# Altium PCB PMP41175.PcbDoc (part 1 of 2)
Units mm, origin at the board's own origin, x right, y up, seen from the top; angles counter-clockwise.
Board outline 50 x 29 mm, 6 copper layers (Top Layer, Signal Layer 1, Signal Layer 2, Signal Layer 3, Signal Layer 4, Bottom Layer), stack 1.56 mm thick; 56 components, 26 nets, 110 pads, 28 vias.
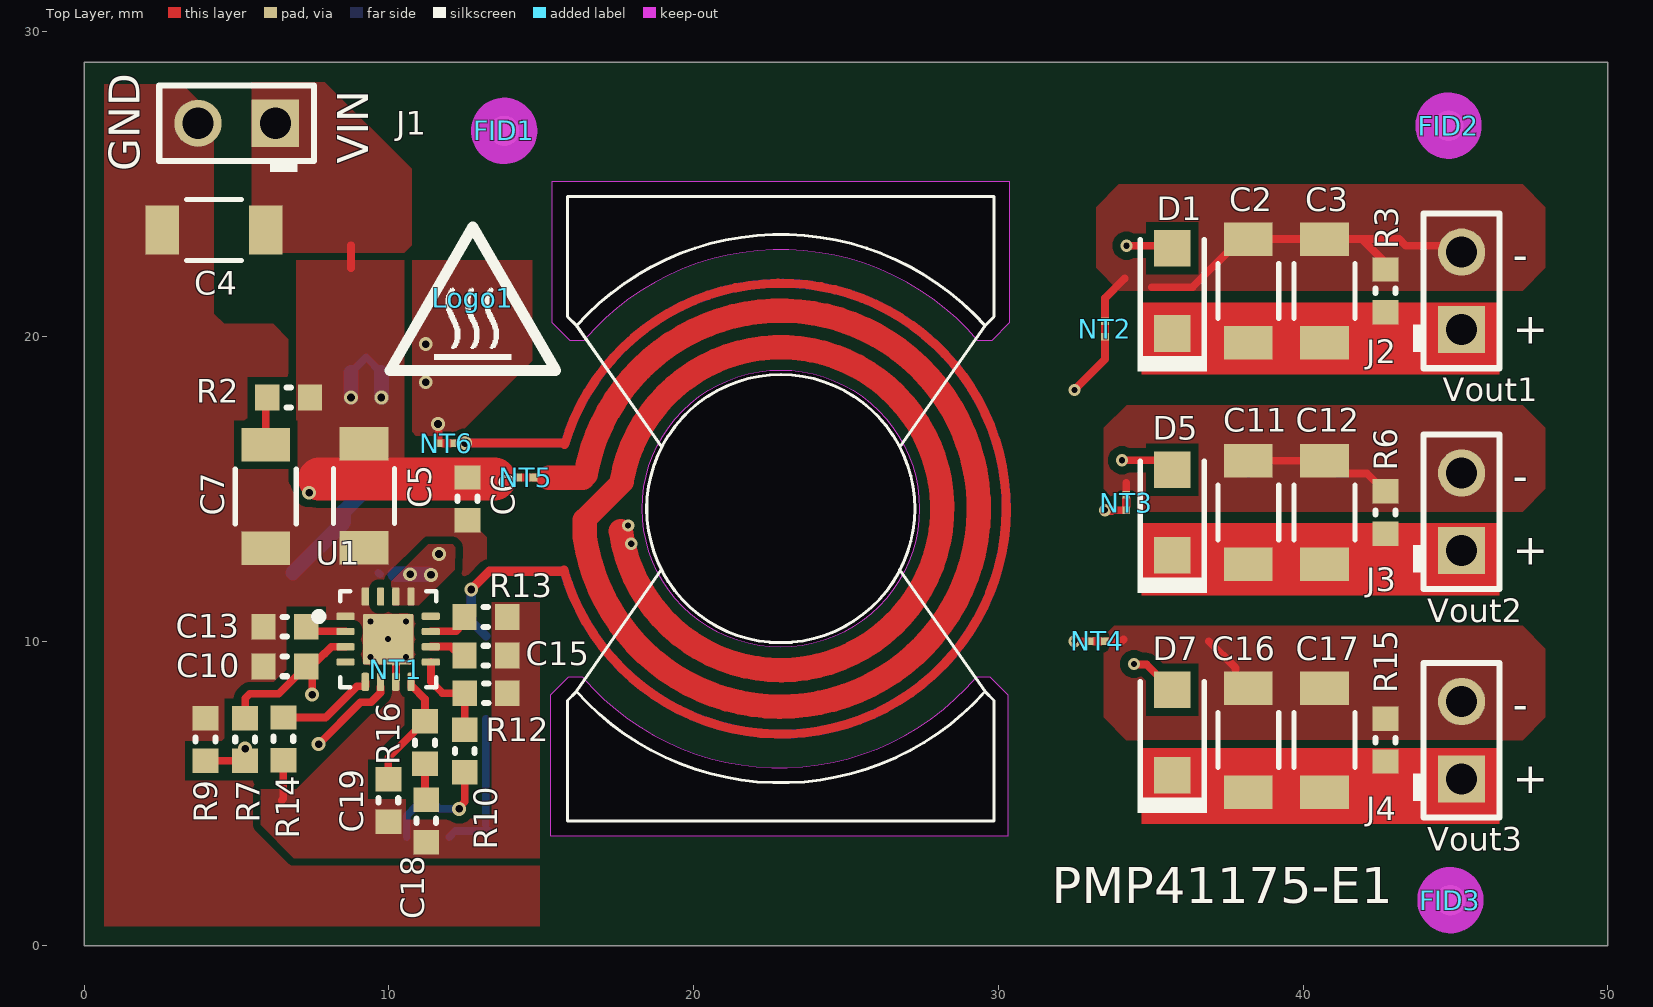
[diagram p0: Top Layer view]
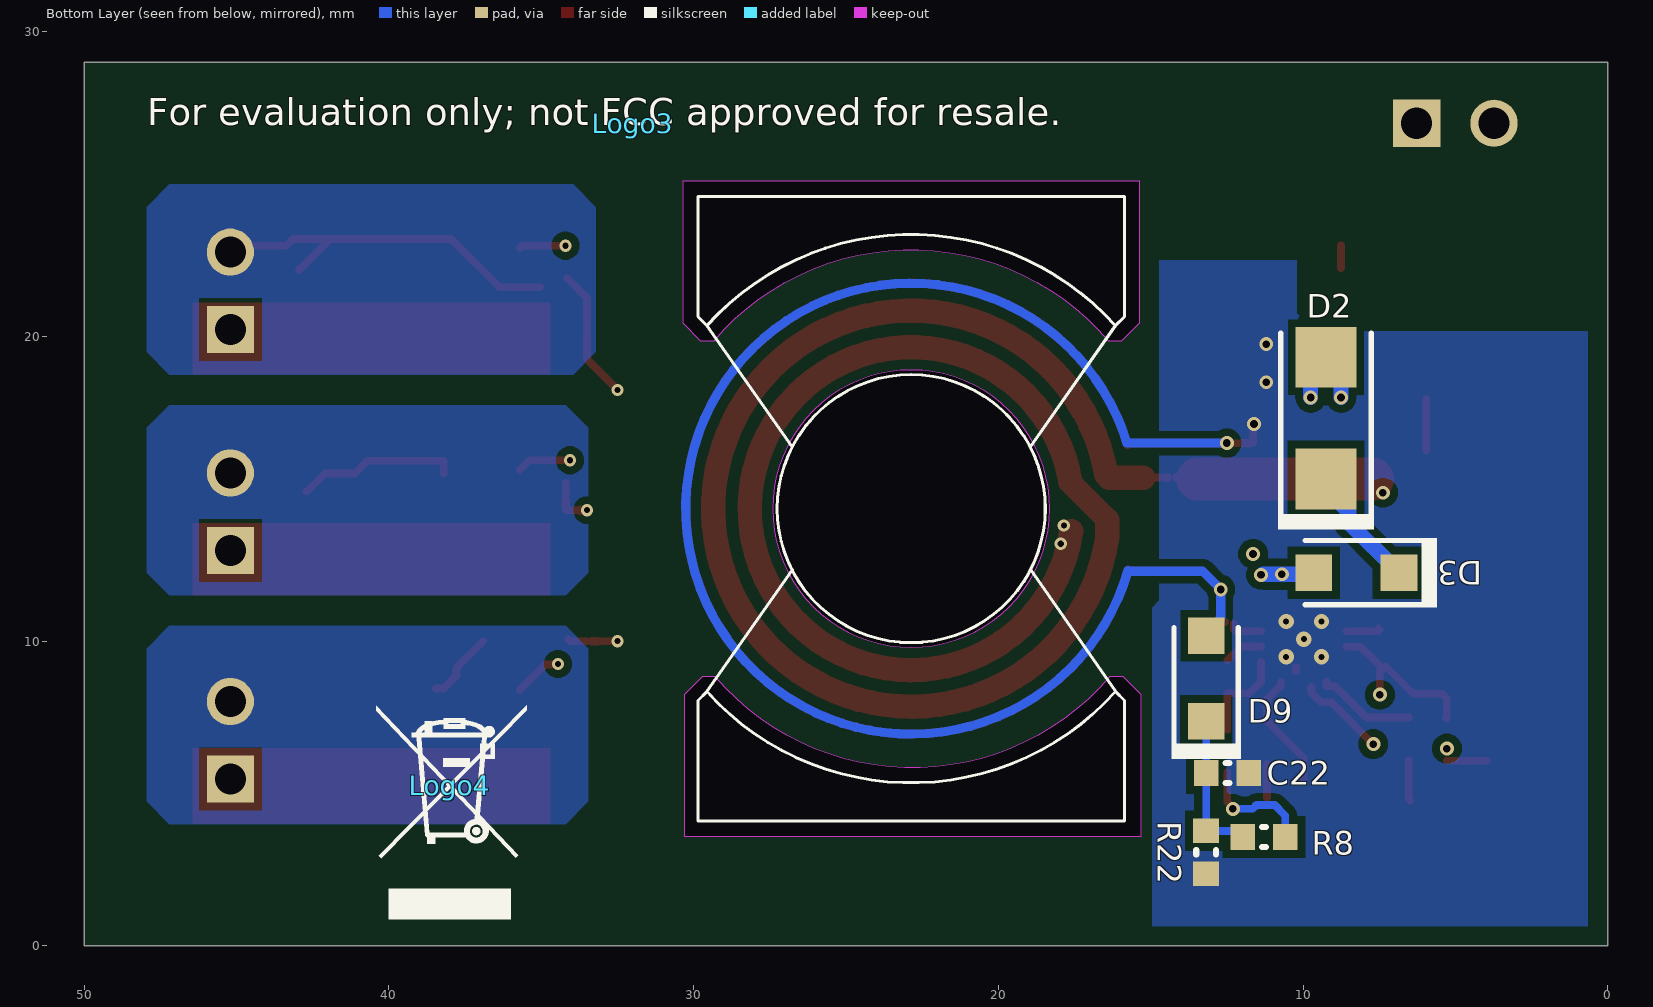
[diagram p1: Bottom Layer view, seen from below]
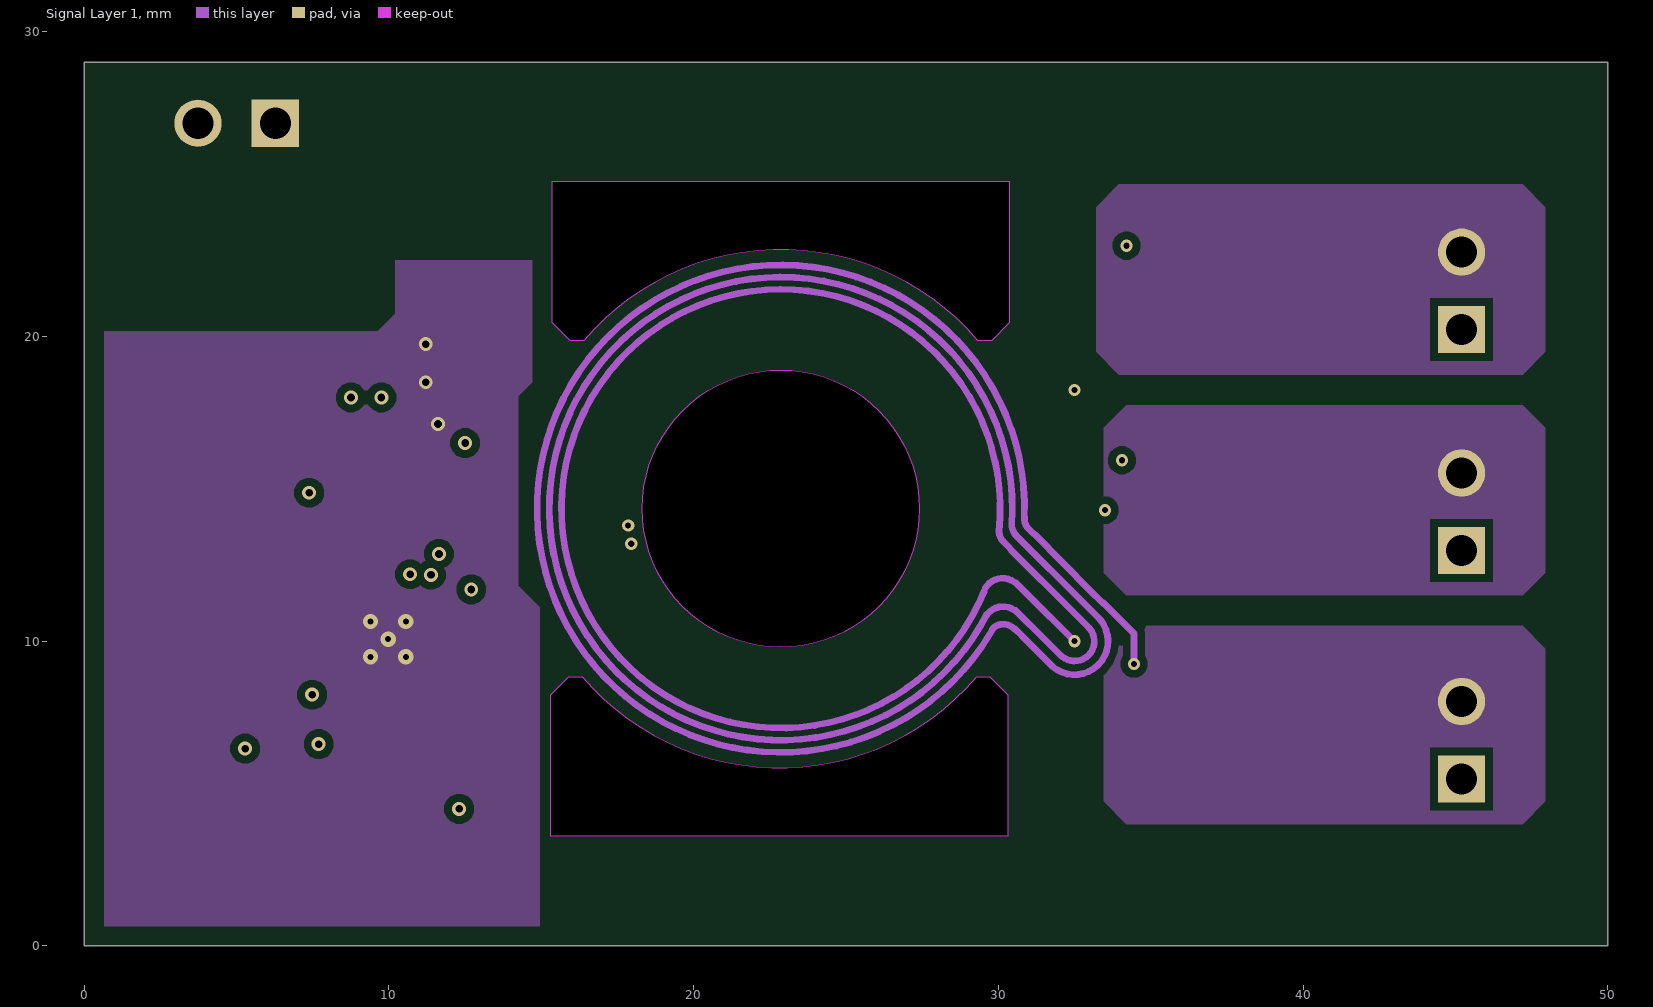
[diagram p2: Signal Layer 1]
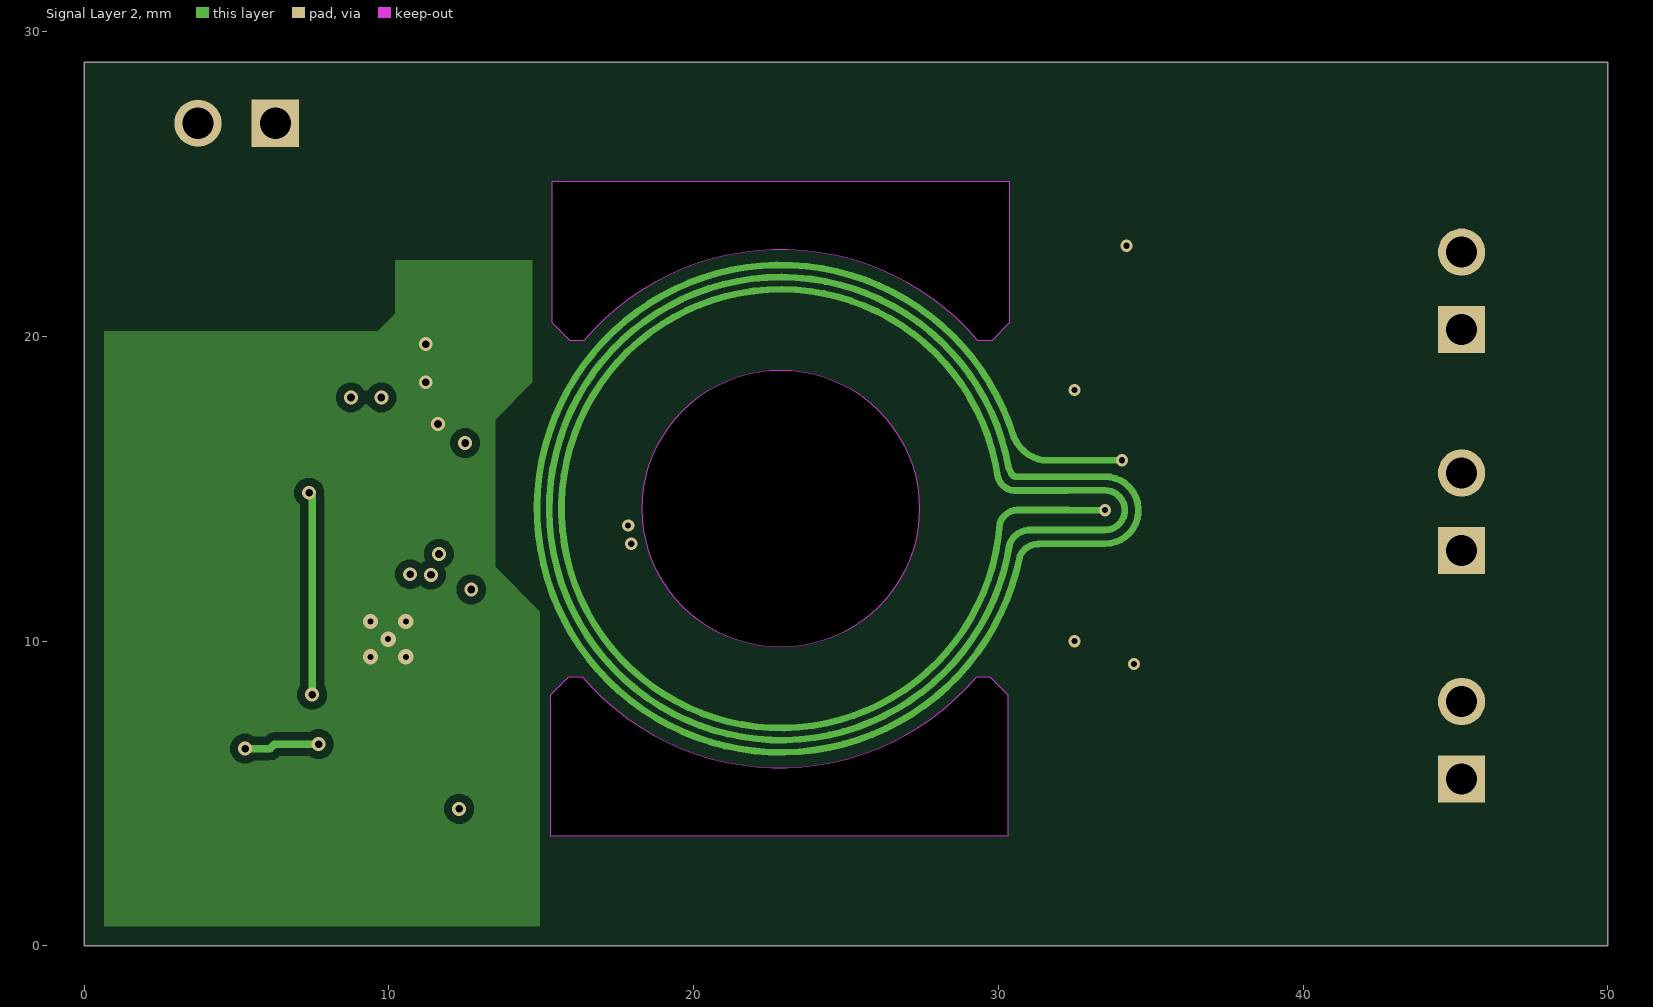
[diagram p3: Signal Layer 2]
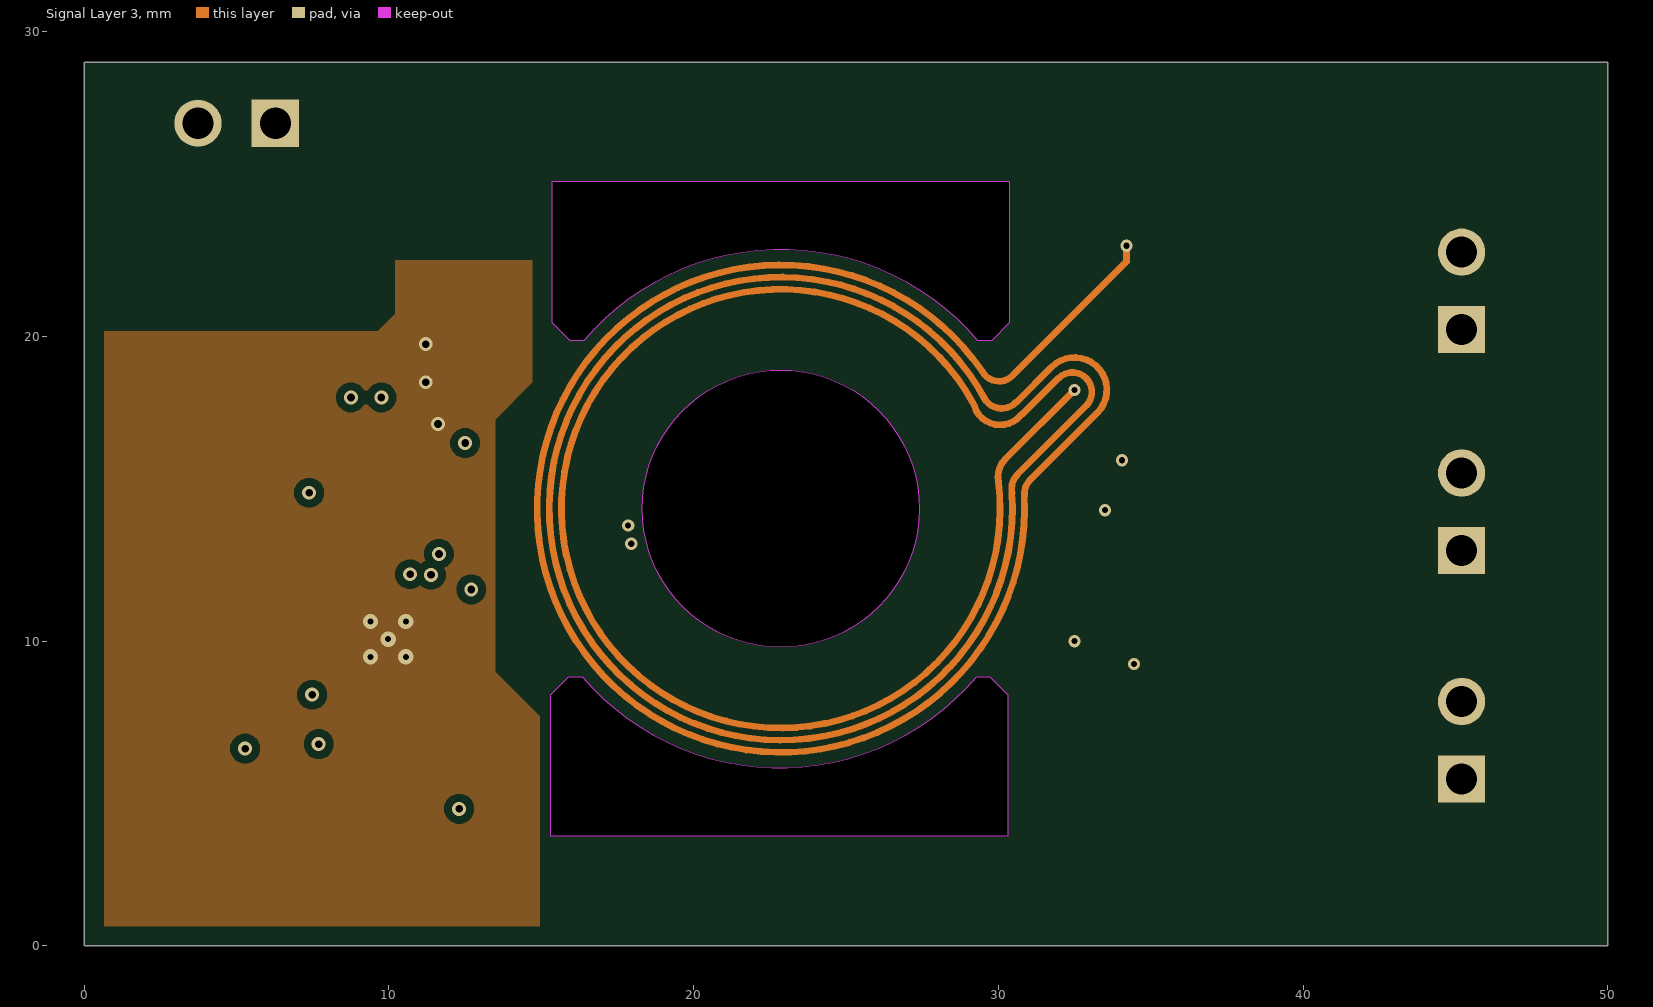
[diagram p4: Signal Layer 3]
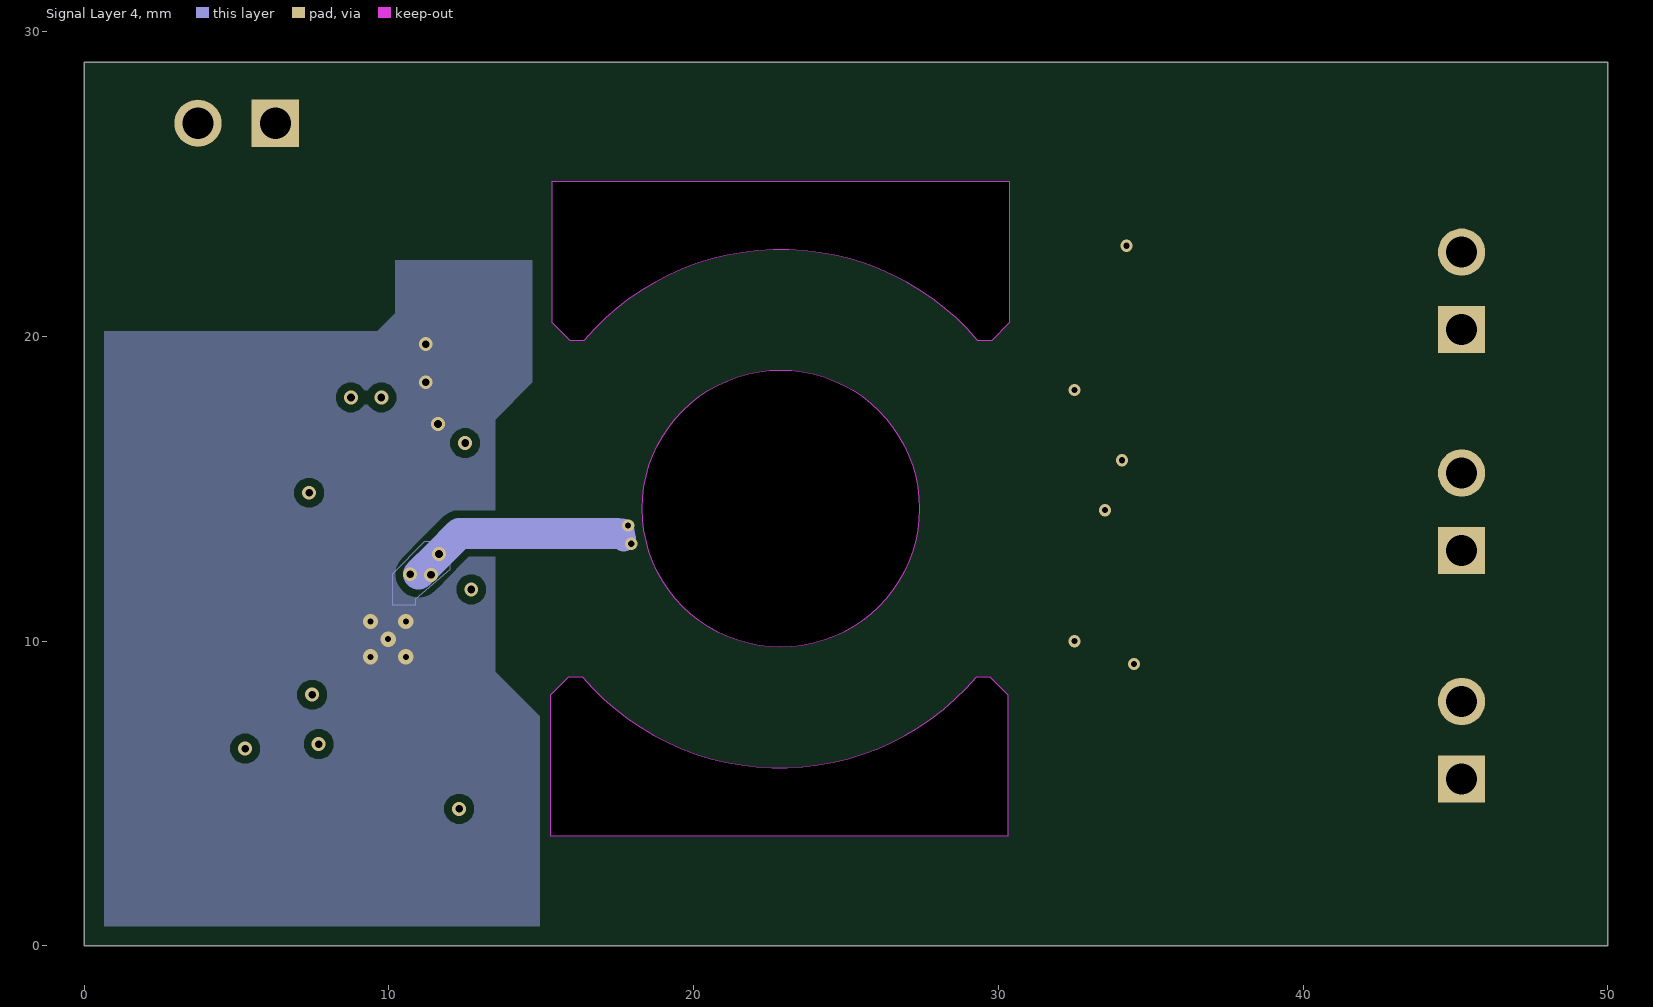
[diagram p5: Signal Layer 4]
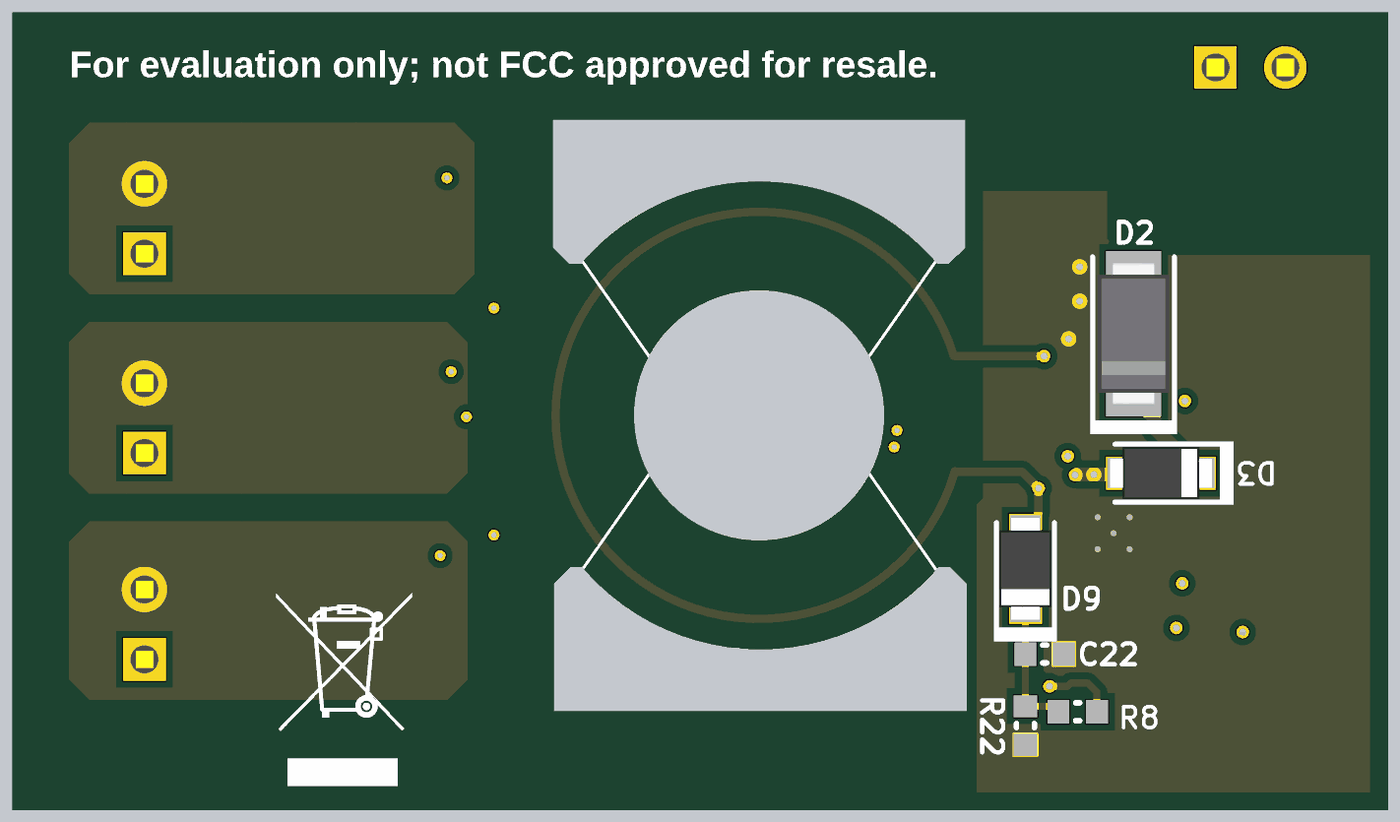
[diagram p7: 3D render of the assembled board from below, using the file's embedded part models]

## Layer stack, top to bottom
Top Solder: solder mask 0.0127, Solder Resist, Dk 3.5
Top Layer: signal copper 0.0356
Dielectric 1: prepreg 0.1778, FR-4 High Tg, Dk 4.2
Signal Layer 1: signal copper 0.0356
Dielectric 2: core 0.3556, FR-4 High Tg, Dk 4.2
Signal Layer 2: signal copper 0.0356
Dielectric 4: prepreg 0.2794, FR-4 High Tg, Dk 4.2
Signal Layer 3: signal copper 0.0356
Dielectric 5: core 0.3556, FR-4 High Tg, Dk 4.2
Signal Layer 4: signal copper 0.0356
Dielectric 3: prepreg 0.1778, FR-4 High Tg, Dk 4.2
Bottom Layer: signal copper 0.0356
Bottom Solder: solder mask 0.0127, Solder Resist, Dk 3.5

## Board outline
0,0 50,0 50,29 0,29
cut-out: 22.86,9.801 cw(c22.86,14.351) 18.31,14.351 cw(c22.86,14.351) 22.86,18.901 cw(c22.86,14.351) 27.41,14.351 cw(c22.86,14.351)
cut-out: 15.951,19.865 15.36,20.451 15.36,25.101 30.36,25.101 30.36,20.451 29.784,19.865 29.769,19.863 29.337,19.863 29.331,19.862 ccw(c22.86,14.351) 16.39,19.863 16.383,19.863
cut-out: 15.316,3.594 15.316,8.244 15.899,8.829 15.907,8.832 16.339,8.832 16.35,8.826 ccw(c22.816,14.344) 29.289,8.835 29.293,8.832 29.724,8.832 30.316,8.244 30.316,3.594

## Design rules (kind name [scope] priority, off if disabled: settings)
AcuteAngle [All] p1: minimum=4.50000000000000E+0001 checktracksonly=FALSE
AssemblyTestPointUsage [All] p1: valid=2
BoardOutlineClearance BoardOutlineClearance_MountingHoles [OnCopper and InComponentClass('Mounting Holes')] p1: gap=1 ignorepadtopadclearanceinfootprint=FALSE
BoardOutlineClearance BoardOutlineClearance_Poly [OnCopper and IsPoly] p2: gap=0.635 ignorepadtopadclearanceinfootprint=FALSE
BoardOutlineClearance [OnCopper and Not InComponentClass('Logo') and not InComponentClass('FiducialMark') and not InRegion(1000,500,4000,800) and not InPoly] p3: gap=0.279 ignorepadtopadclearanceinfootprint=FALSE
Clearance Clearance_Keepouts [((IsTrack Or IsArc) And Not InPoly) And IsFree and IsKeepOut vs ((IsTrack Or IsArc) And Not InPoly) And IsFree and IsKeepOut] p1: gap=0 ignorepadtopadclearanceinfootprint=FALSE
Clearance Clearance_Poly [InPolygon] p2: gap=0.254 ignorepadtopadclearanceinfootprint=TRUE
Clearance Clearance_FiducialMark [IsKeepOut and InComponentClass('FiducialMark') vs IsPad and InComponentClass('FiducialMark')] p3: gap=0 ignorepadtopadclearanceinfootprint=FALSE
Clearance [All] p4: gap=0.2 ignorepadtopadclearanceinfootprint=TRUE
ComponentClearance ComponentClearance_NT [InComponent('NT1')] p1: gap=-0.025 collisioncheckmode=3 verticalgap=0.254 showdistances=FALSE
ComponentClearance ComponentClearance_MountingHoles_FiducialMarks [InComponentClass('Mounting Holes') vs InComponentClass('FiducialMark')] p2: gap=1.27 collisioncheckmode=3 verticalgap=0.254 showdistances=FALSE
ComponentClearance ComponentClearance_Shunt [InComponentClass('Header') vs InComponentClass('Shunt')] p3: gap=0 collisioncheckmode=3 verticalgap=0 showdistances=FALSE
ComponentClearance ComponentClearance_Logo [InComponentClass('Logo')] p4: gap=0.762 collisioncheckmode=3 verticalgap=0.254 showdistances=FALSE
ComponentClearance ComponentClearance_ScrewToNut [(HasFootprint('NY PMS 440 0025 PH')) vs (HasFootprint('Keystone_1902C'))] p5: gap=0.127 collisioncheckmode=3 verticalgap=0.254 showdistances=FALSE
ComponentClearance ComponentClearance_MountingHoles [InComponentClass('Mounting Holes')] p6: gap=2.54 collisioncheckmode=3 verticalgap=2540 showdistances=FALSE
ComponentClearance ComponentClearance_SmallPassives [HasFootprint('0201*') or HasFootprint('0402*') or HasFootprint('0508') or HasFootprint('0603*') or HasFootprint('0612') or HasFootprint('0805*') or HasFootprint('0815*') or HasFootprint('0830*') or HasFootprint('1206*') or HasFootprint('1210*') or HasFootprint('1808*') or HasFootprint('1812*') or HasFootprint('1825*') or HasFootprint('2010*') or HasFootprint('2220*') or HasFootprint('2225*') or HasFootprint('2512*') or HasFootprint('2728*') or HasFootprint('3518*') vs HasFootprint('0201*') or HasFootprint('0402*') or HasFootprint('0508') or HasFootprint('0603*') or HasFootprint('0612') or HasFootprint('0805*') or HasFootprint('0815*') or HasFootprint('0830*') or HasFootprint('1206*') or HasFootprint('1210*') or HasFootprint('1808*') or HasFootprint('1812*') or HasFootprint('1825*') or HasFootprint('2010*') or HasFootprint('2220*') or HasFootprint('2225*') or HasFootprint('2512*') or HasFootprint('2728*') or HasFootprint('3518*')] p7: gap=0.254 collisioncheckmode=3 verticalgap=0.254 showdistances=FALSE
ComponentClearance ComponentClearance_THtoSMT [IsThruComponent vs IsSMTComponent] p8: gap=0.762 collisioncheckmode=3 verticalgap=0.762 showdistances=FALSE
ComponentClearance ComponentClearance_THtoTH [IsThruComponent vs IsThruComponent] p9: gap=0.508 collisioncheckmode=3 verticalgap=0.762 showdistances=FALSE
ComponentClearance [All] p10: gap=0.254 collisioncheckmode=3 verticalgap=0.254 showdistances=FALSE
DiffPairsRouting [All] p1: maxlimit=2.54 minlimit=0.254 mostfreqgap=0.254 toplayer_minwidth=0.381 toplayer_maxwidth=0.381 toplayer_prefwidth=0.381 midlayer1_minwidth=0.381 midlayer1_maxwidth=0.381 midlayer1_prefwidth=0.381 midlayer2_minwidth=0.381 midlayer2_maxwidth=0.381 midlayer2_prefwidth=0.381 midlayer3_minwidth=0.381 midlayer3_maxwidth=0.381 midlayer3_prefwidth=0.381 midlayer4_minwidth=0.381 midlayer4_maxwidth=0.381 midlayer4_prefwidth=0.381 bottomlayer_minwidth=0.381 bottomlayer_maxwidth=0.381 bottomlayer_prefwidth=0.381 maxuncoupledlength=25.4
FabricationTestPointUsage TestPointUsage [All] p1: valid=2 allowmultiple=FALSE
FabricationTestpoint Testpoint [All] p1: side=3 testpointundercomponent=TRUE minsize=1.016 maxsize=2.54 preferedsize=1.524 minholesize=0 maxholesize=1.016 preferedholesize=0.813 testpointgrid=0.025 allowsidetop=TRUE allowsidebottom=TRUE usegrid=TRUE gridtolerance=0
FanoutControl Fanout_LCC [IsLCC] p1: bgadir=Out bgaviamode=Centered fanoutstyle=Auto fanoutdirection=Alternating viagrid=0.025 // Fanout_LCC (Default Rule)
FanoutControl Fanout_BGA [IsBGA] p2: bgadir=Out bgaviamode=Centered fanoutstyle=Auto fanoutdirection=Alternating viagrid=0.025 // Fanout_BGA (Default Rule)
FanoutControl Fanout_Default [All] p4: bgadir=Out bgaviamode=Centered fanoutstyle=Auto fanoutdirection=Alternating viagrid=0.025 // Fanout_Default (Default Rule)
FanoutControl Fanout_Small [(CompPinCount < 5)] p5: bgadir=Out bgaviamode=Centered fanoutstyle=Auto fanoutdirection=OutThenIn viagrid=0.025 // Fanout_Small (Default Rule)
HoleSize [All] p1: absolutevalues=TRUE maxlimit=6.375 minlimit=0.2 maxpercent=80.000 minpercent=20.000
MinimumAnnularRing MinimumAnnularRing_ThermalPadVias [IsVia and InAnyComponent] p1: minimumring=0.15
MinimumAnnularRing [All] p2: minimumring=0.1
MinimumSolderMaskSliver MinimumSolderMaskSliver_Logo [InComponentClass('Logo') vs InComponentClass('Logo')] p1: minsoldermaskwidth=0.018
MinimumSolderMaskSliver [All] p2: minsoldermaskwidth=0.1
PlaneConnect [All] p1: planeconnectstyle=Relief reliefexpansion=0.254 reliefentries=4 reliefconductorwidth=0.254 reliefairgap=0.254
PolygonConnect [All] p1: connectstyle=Direct reliefconductorwidth=0.254 reliefentries=4 polygonreliefangle="90 Angle" airgapwidth=0.254
RoutingVias ThermalPadVias [IsVia and InAnyComponent] p1: holewidth=0.2 width=0.5 viastyle="Through Hole" minholewidth=0.2 minwidth=0.5 maxholewidth=0.33 maxwidth=0.6
RoutingVias [All] p2: holewidth=0.406 width=0.864 viastyle="Through Hole" minholewidth=0.2 minwidth=0.4 maxholewidth=1.016 maxwidth=1.651
SilkToBoardRegionClearance [Not ((IsComment or IsDesignator) And (Hide <> 'False')) and not InRegion(1000,500,4000,800)] p1:
SilkToSilkClearance SilkToSilkClearance_Pb-FreeLogo [(HasFootprint('Pb-Free_Overlay_Medium') OR HasFootprint('Pb-Free_Overlay_Small')) vs (HasFootprint('Pb-Free_Overlay_Medium') OR HasFootprint('Pb-Free_Overlay_Small'))] p1: silktosilkclearance=0
SilkToSilkClearance [All] p2: silktosilkclearance=0.1
SilkToSolderMaskClearance SilkToComponentPadClearance [(IsPad or IsFill or IsRegion) and InAnycomponent] p1: minsilkscreentomaskgap=0 clearancetoexposedcopper=TRUE
SilkToSolderMaskClearance "Silk to Solder Mask Opening" [All] p2: minsilkscreentomaskgap=0.025 clearancetoexposedcopper=FALSE
SolderMaskExpansion [All] p1: expansion=0.05 istentingtop=FALSE
SupplyNets "Schematic Supply Nets_7" [InNet('VBIAS')] p1: voltage=0.000
SupplyNets "Schematic Supply Nets_6" [InNet('GND2')] p2: voltage=0.000
SupplyNets "Schematic Supply Nets_5" [InNet('GND1')] p3: voltage=0.000
SupplyNets "Schematic Supply Nets_4" [InNet('AGND')] p4: voltage=0.000
SupplyNets "Schematic Supply Nets_3" [InNet('GND3')] p5: voltage=0.000
SupplyNets "Schematic Supply Nets_2" [InNet('PGND')] p6: voltage=0.000
SupplyNets "Schematic Supply Nets_1" [InNet('VAUX')] p7: voltage=0.000
UnRoutedNet [All] p1: checkbadconnections=TRUE
Width [All] p1: maxlimit=2.54 minlimit=0.152 preferedwidth=0.254 checkconnectedcopper=TRUE
14 further rules are at their usual default settings.

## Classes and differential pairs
component class PMP41175_Sheet1: C2 C3 C4 C5 C6 C7 C10 C11 C12 C13 C15 C16 C17 C18 C19 C22 D1 D2 D3 D5 D7 D9 J1 J2 J3 J4 NT1 NT2 NT3 NT4 NT5 NT6 R2 R3 R6 R7 R8 R9 R10 R12 R13 R14 R15 R16 R22 T1 U1
component class PMP41175_Hardware: FID1 FID2 FID3 Logo1 Logo3 Logo4 ZZ1 ZZ2 ZZ3 ZZ4
component class FiducialMark: FID1 FID2 FID3
component class AssemblyNote: ZZ1 ZZ2 ZZ3 ZZ4

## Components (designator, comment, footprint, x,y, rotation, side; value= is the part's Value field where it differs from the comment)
C2 "CGA5L1X7R1H106K160AC" 1206_190 38.206,21.5 r90 top value=10uF
C3 "CGA5L1X7R1H106K160AC" 1206_190 40.706,21.5 r90 top value=10uF
C4 "CGA5L1X7R1H106K160AC" 1206_190 4.25,23.5 r180 top value=10uF
C5 "CGA5L1X7R1H106K160AC" 1206_190 9.179,14.773 r270 top value=10uF
C6 "C0603C104K5RACAUTO" 0603L 12.579,14.673 r270 top value=0.1uF
C7 "CGA5L1X7R1H106K160AC" 1206_190 5.956,14.75 r270 top value=10uF
C10 "C0603C104K5RACAUTO" 0603L 6.579,9.173 r180 top value=0.1uF
C11 "CGA5L1X7R1H106K160AC" 1206_190 38.206,14.224 r90 top value=10uF
C12 "CGA5L1X7R1H106K160AC" 1206_190 40.706,14.224 r90 top value=10uF
C13 "06033C105KAT2A" 0603L 6.579,10.473 r180 top value=1uF
C15 "C0603C104K5RACAUTO" 0603L 13.179,9.525 r0 top value=0.1uF
C16 "CGA5L1X7R1H106K160AC" 1206_190 38.206,6.75 r90 top value=10uF
C17 "CGA5L1X7R1H106K160AC" 1206_190 40.706,6.75 r90 top value=10uF
C18 "C0603C223K3RACTU" 0603L 11.224,4.101 r270 top value=0.022uF
C19 "GCM1885C1H101JA16J" 0603L 9.979,4.773 r270 top value=100pF
C22 "GRM188R61E106KA73D" 0603L 12.479,5.673 r180 bottom value=10uF
D1 "PMEG10020ELRX" SOD-123W 35.706,21.5 r90 top value=100V
D2 "3SMAJ5932B-TP" SMA 9.25,17.32 r90 bottom value=20V
D3 "PMEG60T30ELRX" SOD-123W 8.25,12.25 r0 bottom value=60V
D5 "PMEG10020ELRX" SOD-123W 35.706,14.224 r90 top value=100V
D7 "PMEG10020ELRX" SOD-123W 35.706,7 r90 top value=100V
D9 "PMEG10020ELRX" SOD-123W 13.179,8.773 r90 bottom value=100V
FID1 "Fiducial" Fiducial10-20 13.779,26.75 r0 top
FID2 "Fiducial" Fiducial10-20 44.776,26.921 r0 top
FID3 "Fiducial" Fiducial10-20 44.839,1.5 r0 top
J1 "HTSW-102-09-G-S" Samtec_HTSW-102-09-x-S 5,27 r180 top
J2 "HTSW-102-09-G-S" Samtec_HTSW-102-09-x-S 45.206,21.5 r90 top
J3 "HTSW-102-09-G-S" Samtec_HTSW-102-09-x-S 45.206,14.25 r90 top
J4 "HTSW-102-09-G-S" Samtec_HTSW-102-09-x-S 45.206,6.75 r90 top
Logo1 "CAUTION HOT SURFACE" IEC_HotSurface_Small 12.75,21.25 r0 top
Logo3 "FCC disclaimer" FCC_disclaimer 32,27 r180 bottom
Logo4 "WEEE logo" WEEE_Minimum 38,5.25 r180 bottom
NT1 "Net-Tie" Net-Tie_10mil 10.228,9.068 r270 top net-tie
NT2 "Net-Tie" Net-Tie_10mil 33.5,20.25 r270 top net-tie
NT3 "Net-Tie" Net-Tie_10mil 34.196,14.55 r270 top net-tie
NT4 "Net-Tie" Net-Tie_10mil 33.25,10 r180 top net-tie
NT5 "Net-Tie" Net-Tie_10mil 14.491,15.37 r180 top net-tie
NT6 "Net-Tie" Net-Tie_10mil 11.887,16.5 r0 top net-tie
R2 "CRCW0603100RFKEA" 0603L 6.706,18 r0 top value=100
R3 "RC0603JR-0720KL" 0603L 42.706,21.5 r270 top value=20k
R6 "RC0603JR-0720KL" 0603L 42.706,14.224 r270 top value=20k
R7 "RC0603FR-07160KL" 0603L 5.279,6.773 r270 top value=160k
R8 "RC0603FR-0710RL" 0603L 11.279,3.573 r180 bottom value=10.0
R9 "RC0603FR-0753K6L" 0603L 3.979,6.773 r90 top value=53.6k
R10 "RC0603JR-0720KL" 0603L 12.487,6.397 r270 top value=20k
R12 "RC0603JR-073K3L" 0603L 13.187,8.293 r180 top value=3.3k
R13 "ERJ-3GEY0R00V" 0603L 13.179,10.795 r180 top value=0
R14 "RC0603FR-0754K9L" 0603L 6.533,6.794 r90 top value=54.9k
R15 "RC0603JR-0720KL" 0603L 42.706,6.75 r270 top value=20k
R16 "RC0603FR-0710KL" 0603L 11.179,6.673 r90 top value=10.0k
R22 "RC0603FR-0710KL" 0603L 13.179,3.073 r90 bottom value=10.0k
U1 "LM5158QRTERQ1" RTE0016K-MFG 9.972,10.066 r0 top
ZZ1 "This Assembly Note is for PCB labels only" AssemblyNoteLabel 4.353,53.525 r0 top
ZZ2 "These assemblies are ESD sensitive, ESD precautions shall be observed." AssemblyNote 4.353,50.759 r0 top
ZZ3 "These assemblies must be clean and free from flux and all contaminants. Use of no clean flux is not acceptable." AssemblyNote 4.353,48.51 r0 top
ZZ4 "These assemblies must comply with workmanship standards IPC-A-610 Class 2, unless otherwise specified." AssemblyNote 4.353,46.261 r0 top

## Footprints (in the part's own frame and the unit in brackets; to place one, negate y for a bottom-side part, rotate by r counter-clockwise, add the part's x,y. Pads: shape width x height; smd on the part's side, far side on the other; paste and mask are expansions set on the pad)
0603L [mm] "0603 from SM-752 data"
  rect 0.8x0.85 smd: 1(-0.7,0) 2(0.7,0)
  silkscreen extent -0.07,-0.33 0.07,0.33, body extent -0.87,-0.47 0.87,0.47, height 1
1206_190 [mm] "1206_190"
  rect 1.1x1.6 smd: 1(-1.7,0) 2(1.7,0)
  silkscreen extent -0.9,-1 0.9,1, body extent -1.75,-0.95 1.75,0.95, height 1.9
AssemblyNote [mm] "Assembly Note"
AssemblyNoteLabel [mm] "Assembly Note for PCB Labels"
FCC_disclaimer [mm]
Fiducial10-20 [mm]
  round 1 smd mask+0.5: 1(0,0)
  Top Layer keep-out circle w1.178: c0,0 r0.5
IEC_HotSurface_Small [mm]
  silkscreen extent -2.72,-2.36 2.72,2.35
Net-Tie_10mil [mil] "10mil net tie, no solder mask opening, no solder paste"
  rect 10x10 smd paste-5 mask-5: 1(-10,0) 2(10,0)
  Top Layer region: -6,5 6,5 6,-5 -6,-5
RTE0016K-MFG [mm]
  rrect42% 0.6x0.24 smd paste+0 mask+0: 1(-1.4,0.75) 2(-1.4,0.25) 3(-1.4,-0.25) 4(-1.4,-0.75) 9(1.4,-0.75) 10(1.4,-0.25) 11(1.4,0.25) 12(1.4,0.75)
  rrect42% 0.24x0.6 smd paste+0 mask+0: 5(-0.75,-1.4) 6(-0.25,-1.4) 7(0.25,-1.4) 8(0.75,-1.4) 13(0.75,1.4) 14(0.25,1.4) 15(-0.25,1.4) 16(-0.75,1.4)
  rrect6% 1.66x1.66 smd paste-1000 mask+0: 17(0,0)
  silkscreen extent -2.4,-1.58 1.58,1.58, body extent -1.8,-1.8 1.8,1.8, height 0.25
Samtec_HTSW-102-09-x-S [mm] "Header, 2x1, 2.54mm, TH"
  rect 1.55x1.55 hole 1.02: 1(-1.27,0)
  round 1.55 hole 1.02: 2(1.27,0)
  silkscreen extent -2.54,-1.24 2.54,1.6, body extent -2.54,-1.24 2.54,1.24, height 8.38
SMA [mm] "Molded Diode, 2-Leads, Body 4.3x2.6mm, IPC Medium Density, based on OnSemi component dimensions and land pattern"
  rect 2x2 smd: 1(-2,0) 2(2,0)
  silkscreen extent -3.66,-1.57 2.79,1.57, body extent -2.6,-1.3 2.6,1.3, height 2.42
SOD-123W [mm] "NXP recommended land pattern"
  rect 1.2x1.2 smd paste-0.05: 1(-1.4,0) 2(1.4,0)
  silkscreen extent -2.64,-1.14 1.68,1.14, body extent -1.85,-0.95 1.85,0.95, height 1.1
WEEE_Minimum [mm] "WEEElie bin"
  silkscreen extent -2.42,-4.38 2.52,2.65

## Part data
C2 C3 C4 C5 C7 C11 C12 C16 C17: library part CMP-0085950-1, "CAP, CERM, 10 µF, 50 V,+/- 10%, X7R, AEC-Q200 Grade 1, 1206", Cap_Case=1206, Manufacturer=TDK, TempCo=X7R, Tolerance_%=10%, Value2=50V, ValueDisplayed=10µF
C6 C10 C15: library part CMP-0079602-1, "CAP, CERM, 0.1 µF, 50 V,+/- 10%, X7R, AEC-Q200 Grade 1, 0603", Cap_Case=0603, Manufacturer=Kemet, Supplier Part Number 1=399-6856-1-ND, TempCo=X7R, Tolerance_%=10%, Value2=50V, ValueDisplayed=0.1µF
C13: library part CMP-0006754-4, "CAP, CERM, 1 uF, 25 V, +/- 10%, X7R, 0603", Cap_Case=0603, Manufacturer=AVX, Supplier Part Number 1=478-10046-1-ND, TempCo=X7R, Tolerance_%=10%, Value1=Unknown, Value2=25V, ValueDisplayed=1uF
C18: library part CMP-0006899-4, "CAP, CERM, 0.022 uF, 25 V, +/- 10%, X7R, 0603", Cap_Case=0603, Manufacturer=Kemet, Supplier Part Number 1=399-1094-1-ND, TempCo=X7R, Tolerance_%=10%, Value1=Unknown, Value2=25V, ValueDisplayed=0.022uF
C19: library part CMP-0750041-1, "CAP, CERM, 100 pF, 50 V,+/- 5%, C0G/NP0, AEC-Q200 Grade 1, 0603", Cap_Case=0603, Manufacturer=MuRata, TempCo=C0G/NP0, Tolerance_%=5%, Value2=50V, ValueDisplayed=100pF
C22: library part CMP-0860569-1, "CAP, CERM, 10 µF, 25 V,+/- 10%, X5R, 0603", Cap_Case=0603, Manufacturer=MuRata, TempCo=X5R, Tolerance_%=10%, Value2=25V, ValueDisplayed=10µF
D1 D5 D7 D9: library part CMP-0028977-2, "Diode, Schottky, 100 V, 2 A, AEC-Q101, SOD-123W", Manufacturer=Nexperia, Value1=2A, Value2=0.83V
D2: library part CMP-0005511-4, "Diode, Zener, 20 V, 3 W, SMA", Manufacturer="Micro Commercial Components", Power_W=3W
D3: library part CMP-0085903-1, "Diode, Schottky, 60 V, 3 A, AEC-Q101, SOD-123W", Manufacturer=Nexperia, Value1=3A, Value2=0.62V
FID1 FID2 FID3: library part CMP-0077181-1, "Fiducial mark.  There is nothing to buy or mount.", Manufacturer=N/A
J1 J2 J3 J4: library part CMP-0075626-1, "Header, 100mil, 2x1, Gold, TH", Color=Black, Manufacturer=Samtec
Logo1: library part CMP-0074837-2, "IEC 61010-1 Hot Surface Warning", Manufacturer="Texas Instruments"
Logo3: library part CMP-0074847-1, "FCC_disclaimer"
Logo4: library part CMP-0074769-4, Manufacturer="Texas Instruments"
NT1 NT2 NT3 NT4 NT5 NT6: library part CMP-0078142-6, "Single point connection between nets.", Manufacturer=N/A
R2: library part CMP-0021991-4, "RES, 100, 1%, 0.1 W, AEC-Q200 Grade 0, 0603", Manufacturer=Vishay-Dale, Power_W=100mW, Supplier Part Number 1=541-100HCT-ND, TempCo="100 ppm/C", Tolerance_%=1%, Value2=0.1W, Value_Code=100R, ValueDisplayed=100
R3 R6 R10 R15: library part CMP-0025900-5, "RES, 20 k, 5%, 0.1 W, 0603", Manufacturer=Yageo, Power_W=100mW, Supplier Part Number 1=311-20KGRCT-ND, TempCo="100 ppm/C", Tolerance_%=5%, Value2=0.1W, Value_Code=20k0, ValueDisplayed=20k
R7: library part CMP-0022820-4, "RES, 160 k, 1%, 0.1 W, 0603", Manufacturer=Yageo, Power_W=100mW, Supplier Part Number 1=311-160KHRCT-ND, TempCo="100 ppm/C", Tolerance_%=1%, Value2=0.1W, Value_Code=160k
R8: library part CMP-0022751-4, "RES, 10.0, 1%, 0.1 W, 0603", Manufacturer=Yageo, Power_W=100mW, Supplier Part Number 1=311-10.0HRCT-ND, TempCo="100 ppm/C", Tolerance_%=1%, Value2=0.1W, Value_Code=10R0, ValueDisplayed=10.0
R9: library part CMP-0023176-5, "RES, 53.6 k, 1%, 0.1 W, 0603", Manufacturer=Yageo, Power_W=100mW, Supplier Part Number 1=311-53.6KHRCT-ND, TempCo="100 ppm/C", Tolerance_%=1%, Value2=0.1W, Value_Code=53k6, ValueDisplayed=53.6k
R12: library part CMP-0025918-5, "RES, 3.3 k, 5%, 0.1 W, 0603", Manufacturer=Yageo, Power_W=100mW, Supplier Part Number 1=311-3.3KGRCT-ND, TempCo="100 ppm/C", Tolerance_%=5%, Value2=0.1W, Value_Code=3k30, ValueDisplayed=3.3k
R13: library part CMP-0025874-4, "RES, 0, 5%, 0.1 W, AEC-Q200 Grade 0, 0603", Manufacturer=Panasonic, Power_W=100mW, Supplier Part Number 1=P0.0GCT-ND, TempCo="600 ppm/C", Tolerance_%=5%, Value2=0.1W, Value_Code=0000, ValueDisplayed=0
R14: library part CMP-0023180-5, "RES, 54.9 k, 1%, 0.1 W, 0603", Manufacturer=Yageo, Power_W=100mW, Supplier Part Number 1=311-54.9KHRCT-ND, TempCo="100 ppm/C", Tolerance_%=1%, Value2=0.1W, Value_Code=54k9, ValueDisplayed=54.9k
R16 R22: library part CMP-0022746-5, "RES, 10.0 k, 1%, 0.1 W, 0603", Manufacturer=Yageo, Power_W=100mW, Supplier Part Number 1=311-10.0KHRCT-ND, TempCo="100 ppm/C", Tolerance_%=1%, Value2=0.1W, Value_Code=10k0, ValueDisplayed=10.0k
U1: library part CMP-0091836-5, "2.2-MHz Wide VIN 85-V Boost/Sepic/Flyback Converter with Dual Random Spread Spectrum", Manufacturer="Texas Instruments", Max Supply Voltage=60V, Min Supply Voltage=1.5V, Nominal Supply Current=670uA, Operating Temperature Range="-40°C to +150°C", Output Voltage=83V, Switching Frequency=100-2200kHz
ZZ1: library part CMP-0003616-3
ZZ2: library part CMP-0077236-1
ZZ3: library part CMP-0077237-1
ZZ4: library part CMP-0077238-1

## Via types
v1: diameter 0.457, hole 0.254, Top Layer to Bottom Layer, 15 vias
v2: diameter 0.4, hole 0.2, Top Layer to Bottom Layer, 8 vias
v3: diameter 0.5, hole 0.2, Top Layer to Bottom Layer, 5 vias

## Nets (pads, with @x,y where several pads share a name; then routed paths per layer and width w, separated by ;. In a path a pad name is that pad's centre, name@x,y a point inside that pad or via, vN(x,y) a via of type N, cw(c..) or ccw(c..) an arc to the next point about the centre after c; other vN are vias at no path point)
AGND: C15.2 C18.2 C19.2 NT1.2 R12.1 R13.1 R14.1 U1.7 | length 1.3
  Top Layer w0.254: 6.479,4.773 6.533,4.827 R14.1@6.533,6.094
COMP: C19.1 R16.2 U1.8 | length 3.9
  Top Layer w0.254: C19.1@9.979,5.473 9.979,6.173 R16.2@11.179,7.373 11.179,8.102 10.781,8.5 10.736,8.5 10.729,8.507 U1.8@10.729,8.673
FB: R10.1 R12.2 U1.9 | length 3.1
  Top Layer w0.254: U1.9@11.379,9.323 11.379,8.673 11.759,8.293 R12.2@12.487,8.293 R10.1@12.487,7.097
GND1: C2.2 C3.2 J2.2 NT2.1 R3.1 | length 14.6
  Top Layer w0.254: NT2.1@33.5,20.504 33.5,21.261 34.146,21.907 ; 35.039,21.614 36.37,21.614 37.956,23.2 C2.2@38.206,23.2 C3.2@40.706,23.2 41.931,23.2 ; R3.1@42.956,22.2 42.931,22.2 41.931,23.2 ; J2.2@45.706,22.77 45.495,22.981 43.371,22.981 43.152,23.2 41.931,23.2
GND2: C11.2 C12.2 J3.2 NT3.1 R6.1 | length 5.7
  Top Layer w0.254: NT3.1@34.196,14.804 34.2,15.2 ; C11.2@38.206,15.5 C11.2@38.206,15.924 C12.2@40.706,15.924 41.129,15.501 42.104,15.501 42.681,14.924 R6.1@42.706,14.924
GND3: C16.2 C17.2 J4.2 NT4.1 R15.1 | length 3
  Top Layer w0.254: NT4.1@33.504,10 34.051,10 34.108,10.057 ; 36.909,9.997 37.783,9.123 37.783,8.873 C16.2@38.206,8.45 C16.2@38.456,8.45
MODE: R13.2 U1.11 | length 1.1
  Top Layer w0.254: U1.11@11.379,10.323 12.206,10.323 12.274,10.391 R13.2@12.274,10.568 ; R13.2@12.56,10.634 R13.2@12.585,10.634
NetC7_1: C7.1 R2.1 | length 1.7
  Top Layer w0.254: C7.1@5.956,16.25 R2.1@5.956,17.95
NetC18_1: C18.1 R16.1 | length 1.1
  Top Layer w0.254: C18.1@11.179,4.873 R16.1@11.179,5.973
NetD1_2: D1.2 NT2.2 | length 167
  Top Layer w0.254: v2(32.5,18.25) 33.5,19.25 NT2.2@33.5,19.996 ; v2(34.207,22.981) 35.625,22.981 D1.2@35.706,22.9
  Signal Layer 3 w0.22: 15.373,13.031 ccw(c22.86,14.351) 30.444,14.87 ; 15.375,13.031 cw(c22.86,14.351) 29.546,17.964 ; 29.265,17.585 ccw(c29.474,17.651) 29.283,17.542 ccw(c30.06,18.003) 30.616,17.291 30.793,17.468 30.81,17.468 31.979,18.634 cw(c32.43,18.18) 32.884,17.728 30.637,15.483 ccw(c31.118,15.001) 30.442,14.912 30.447,14.871 ; 29.264,17.585 ccw(c27.927,17.167) 29.152,17.847 ccw(c22.858,14.351) 30.004,15.229 ; 29.453,18.882 ccw(c22.86,14.351) 30.615,12.387 ccw(c22.86,14.351) 30.849,14.77 ; 29.483,18.842 ccw(c30.022,19.154) 30.473,18.724 ; 29.547,17.965 ccw(c30.11,18.29) 30.581,17.842 ; 30.002,15.261 cw(c30.79,15.4) 30.224,15.966 ; 30.226,15.976 v2(32.5,18.25) ; 30.5,18.75 34.207,22.457 v2(34.207,22.981) ; 30.619,17.869 31.751,19 cw(c32.5,18.25) 33.252,17.503 31.002,15.253 ; 30.866,14.779 cw(c31.471,14.858) 31.04,15.29
NetD2_1: D2.1 D3.1 | length 3.7
  Bottom Layer w0.5: D3.1@6.85,12.25 8.5,13.9 8.5,14.25 D2.1@9.25,15
NetD5_2: D5.2 NT3.2 | length 168.1
  Top Layer w0.254: v2(33.5,14.3) 33.504,14.296 NT3.2@34.196,14.296 ; v2(34.056,15.938) D5.2@35.256,15.938 ; D5.2@35.392,15.938 D5.2@35.706,15.624
  Top Layer w0.305: v2(33.5,14.3) 33.721,14.3
  Signal Layer 2 w0.22: 29.922,12.948 29.932,13.014 cw(c30.149,12.982) 29.94,13.05 ; 30.042,13.849 cw(c22.86,14.351) 29.983,15.398 ccw(c30.565,15.544) 30.622,14.947 32.249,14.947 ; 30.044,13.863 cw(c30.661,13.66) 30.718,14.307 32.305,14.307 ; 30.365,13.169 cw(c31.03,12.95) 31.092,13.647 ; 30.366,13.162 cw(c22.86,14.351) 30.345,15.671 30.427,15.488 ccw(c30.608,15.631) 30.609,15.4 32.196,15.4 ; 30.482,16.783 ccw(c31.658,17.162) 31.468,15.941 ccw(c31.5,16.158) 31.498,15.938 31.5,15.938 v2(34.056,15.938) ; 30.515,16.677 ccw(c22.86,14.351) 30.699,12.756 ; 30.701,12.776 cw(c31.306,12.538) 31.306,13.188 ; 31.082,13.647 32.668,13.647 ; 31.35,13.2 33.497,13.2 ccw(c33.5,14.3) 33.489,15.4 32.196,15.4 ; 31.373,14.95 33.5,14.95 cw(c33.5,14.3) 33.5,13.65 31.413,13.65 ; 31.402,15.4 32.196,15.4 ; 31.413,14.3 v2(33.5,14.3)
NetD7_2: D7.2 NT4.2 | length 168.6
  Top Layer w0.254: v2(32.5,10) NT4.2@32.996,10 ; v2(34.456,9.25) 34.474,9.232 34.874,9.232 D7.2@35.706,8.4
  Signal Layer 1 w0.22: 29.536,11.654 cw(c22.86,14.351) 30.021,13.598 ; 29.575,11.743 cw(c30.138,11.418) 30.51,11.95 ; 29.59,10.811 cw(c30.153,10.486) 30.526,11.018 ; 29.632,10.901 cw(c22.86,14.351) 30.441,13.821 ; 30.025,13.652 ccw(c30.51,13.61) 30.157,13.274 ; 30.178,13.251 30.39,13.039 ; 30.418,12.998 31.418,11.998 ; 30.445,13.861 ccw(c30.93,13.819) 30.577,13.483 ; 30.505,10.418 ccw(c30.162,10.073) 29.861,10.455 ccw(c29.997,10.283) 29.805,10.389 29.718,10.232 cw(c22.86,14.351) 30.855,14.072 ; 30.544,10.406 30.756,10.193 ; 30.553,13.502 30.695,13.36 ; 30.565,11.013 31.565,10.013 ; 30.583,11.907 30.796,11.695 ; 30.68,13.373 31.68,12.373 ; 30.7,11.8 31.7,10.8 ; 30.779,10.169 31.779,9.169 ccw(c32.5,10) 33.23,10.823 32.23,11.823 31.23,12.823 ; 30.856,14.068 ccw(c31.341,14.025) 30.989,13.69 31.13,13.548 ; 30.918,12.498 31.918,11.498 32.918,10.498 cw(c32.5,10) 32.082,9.502 ; 31.065,10.513 32.065,9.513 32.099,9.486 ; 31.2,13.5 33.028,11.65 33.425,11.253 33.453,11.253 34.456,10.25 v2(34.456,9.25) ; 31.5,11 v2(32.5,10)
NetD9_2: D9.2 NT6.2 | length 99.5
  Top Layer w0.254: NT6.2@12.141,16.5 v1@12.675,16.5 ; 14.675,16.5 14.679,16.504
  Top Layer w0.3: v1@12.679,16.504 12.683,16.5 14.675,16.5 ; v1(12.7,11.7) 13.294,12.294 15.75,12.294 ; 14.679,16.504 15.75,16.504 ; 15.74,12.336 ccw(c22.86,14.351) 15.765,16.453
  Bottom Layer w0.3: v1@12.679,16.504 15.75,16.504 ; v1@12.7,11.627 12.7,10.799 12.729,10.77 12.729,10.623 D9.2@13.179,10.173 ; v1(12.7,11.7) 13.294,12.294 15.75,12.294 ; 15.747,12.311 ccw(c22.86,14.351) 15.783,16.515
  other v1: 12.5,16.504
NetR8_2: R8.2 R10.2 | length 3.9
  Top Layer w0.254: v1(12.304,4.498) 12.304,4.553 12.487,4.736 R10.2@12.487,5.697
  Bottom Layer w0.254: R8.2@10.579,3.573 10.579,4.273 10.929,4.623 11.527,4.623 11.652,4.498 v1(12.304,4.498)
PGND: C4.2 C5.2 C6.2 C7.2 C10.2 C13.2 C22.2 J1.2 NT1.1 NT6.1 R9.2 R22.1 U1.1 U1.16 U1.17 | length 0.4
  Top Layer w0.254: NT6.1@11.633,16.5 11.636,16.866
  other v1: 11.608,17.13 11.206,18.5 11.206,19.75
  other v3: 9.392,9.486 10.552,9.486 9.972,10.066 9.392,10.646 10.552,10.646
RT: R14.2 U1.5 | length 3.3
  Top Layer w0.254: R14.2@6.533,7.494 7.919,7.494 8.948,8.523 9.222,8.523 9.229,8.53 U1.5@9.229,8.673
SS: C15.1 U1.10 | length 1.3
  Top Layer w0.254: U1.10@11.379,9.823 12.029,9.823 C15.1@12.479,9.373
SW: D3.2 NT5.1 U1.13 U1.14 | length 83.1
  Top Layer w0.254: NT5.1@14.745,15.37 15.494,15.37
  Top Layer w0.75: 16.406,13.979 17.663,15.236
  Top Layer w0.8: 15.24,15.37 16.354,15.37 ; 16.423,13.446 ccw(c22.86,14.351) 16.459,15.48 ; 16.423,13.499 16.423,13.979 ; 17.612,13.613 ccw(c22.86,14.351) 17.641,15.271
  Signal Layer 4 w0.8: 17.661,13.62 ccw(c22.86,14.351) 17.706,13.349
  Signal Layer 4 w1.016: 10.971,12.198 v1(11.638,12.865) 12.306,13.533 ; 12.319,13.533 17.5,13.533
  Bottom Layer w0.254: D3.2@9.65,12.25 D3.2@9.702,12.198
  Bottom Layer w0.5: D3.2@10.202,12.198 v1@11.302,12.198
  other v1: 10.694,12.198 11.375,12.18
  other v2: 17.95,13.2 17.85,13.8
UVLO: R7.2 R9.1 U1.6 | length 6.7
  Top Layer w0.254: R9.1@3.979,6.073 R7.2@5.279,6.073 ; v1(7.693,6.621) 9.066,7.994 9.407,7.994 9.722,8.309 U1.6@9.722,8.493
  Signal Layer 2 w0.254: v1(5.279,6.473) 6.092,6.473 6.24,6.621 v1(7.693,6.621)
VAUX: C22.1 D9.1 R8.1 R22.2 | length 4.9
  Bottom Layer w0.254: R8.1@11.979,3.573 12.179,3.773 R22.2@13.179,3.773 R22.2@13.279,3.773 ; R22.2@13.179,3.973 D9.1@13.179,7.448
